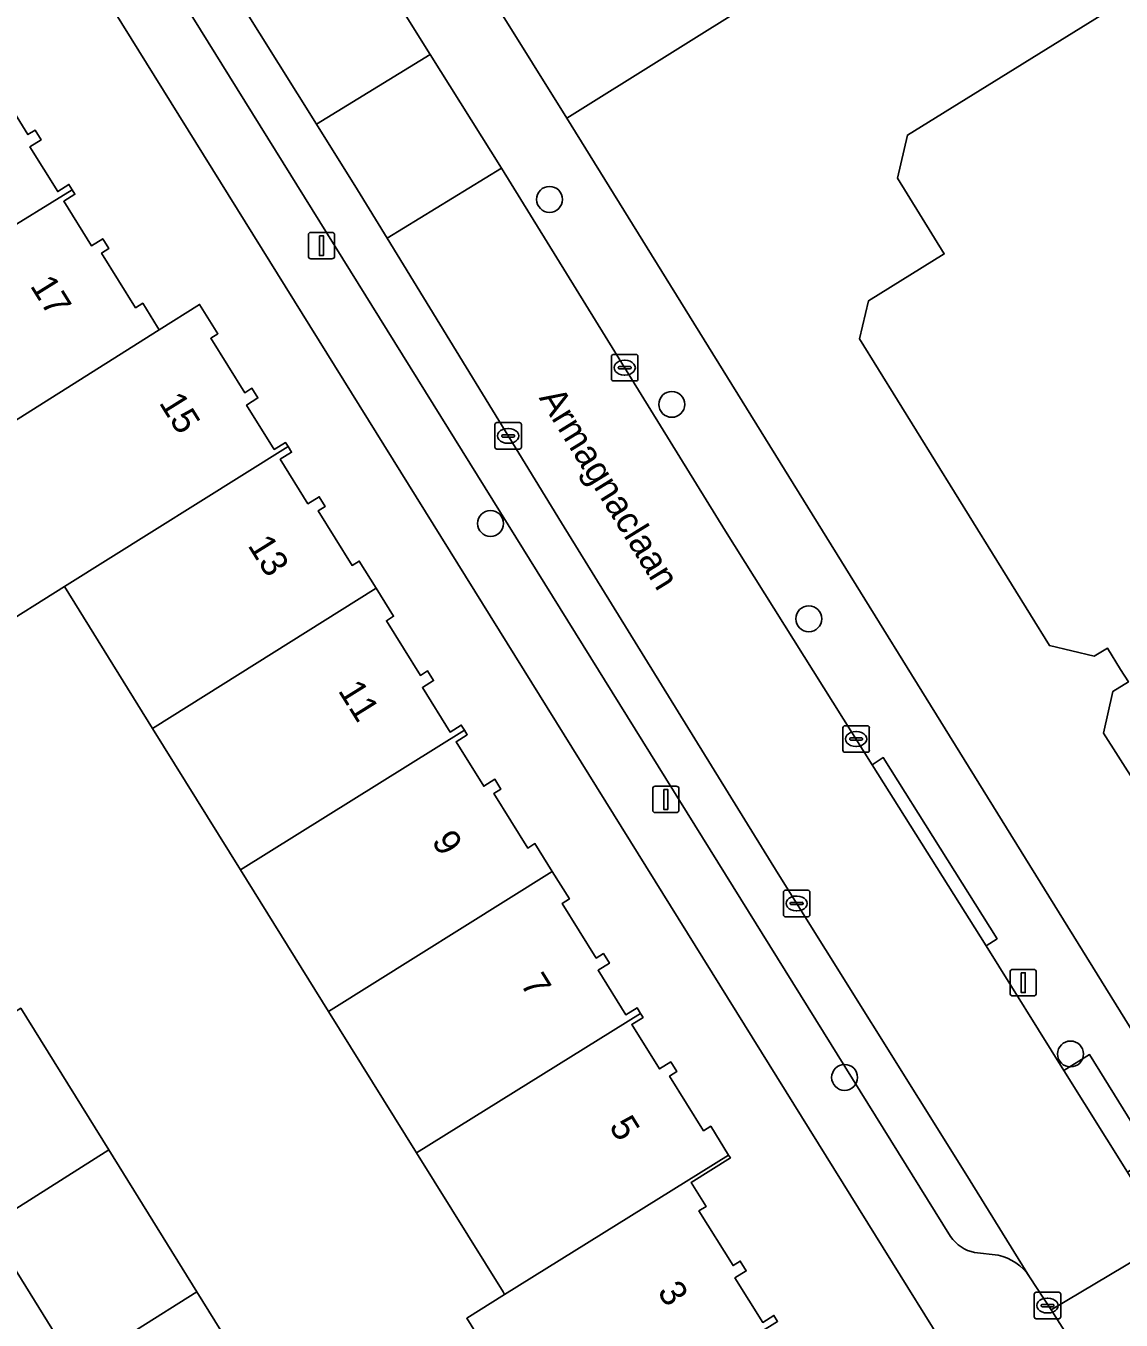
# Model space of a CAD drawing. Extents: x 157767 to 159172, y 387839 to 389425.
# Drawn here: x 158641.28 to 158682.64, y 388021.79 to 388070.65 of the extents above; entities that cross this region are included whole.
import ezdxf

# ---------------------------------------------------------------- set-up
doc = ezdxf.new("R2010")
doc.units = 0
for name, color, linetype in [('IMGEO_Boom', 7, 'Continuous'), ('IMGEO_Erf', 7, 'Continuous'), ('IMGEO_Kolk', 7, 'Continuous'), ('IMGEO_Lichtmast', 7, 'Continuous'), ('IMGEO_Openbare_ruimte_label', 7, 'Continuous'), ('IMGEO_Pand', 7, 'Continuous'), ('IMGEO_Pand_nummerreeks', 7, 'Continuous'), ('IMGEO_Parkeervlak_open', 7, 'Continuous'), ('IMGEO_Rijbaan_lokaal_gesloten', 7, 'Continuous'), ('IMGEO_Rijbaan_lokaal_open', 7, 'Continuous'), ('IMGEO_Voetpad_open', 7, 'Continuous')]:
    doc.layers.add(name, color=color, linetype=linetype)

msp = doc.modelspace()

# ---------------------------------------------------------------- linework, layer by layer
at = {"layer": 'IMGEO_Boom'}
for centre in [(158661.055, 388064.097), (158665.671, 388056.36), (158658.827, 388051.865), (158670.846, 388048.268), (158680.731, 388031.841), (158672.199, 388030.956)]:
    msp.add_circle(centre, 0.489, dxfattribs=at)
at = {"layer": 'IMGEO_Erf'}
for points in [[(158737.779, 388053.263), (158742.17, 388056.603), (158742.727, 388058.158), (158738.82, 388064.497), (158716.081, 388101.143), (158691.111, 388085.534), (158661.715, 388067.158), (158686.368, 388027.385), (158687.799, 388025.086)], [(158683.812, 388041.071), (158681.976, 388043.955), (158682.334, 388045.526), (158682.916, 388045.887), (158682.624, 388046.358), (158682.123, 388047.164), (158681.629, 388046.858), (158679.935, 388047.256), (158672.765, 388058.828), (158673.104, 388060.27), (158675.965, 388062.042), (158674.193, 388064.902), (158674.573, 388066.522), (158688.823, 388075.351)], [(158677.387, 388018.539), (158643.677, 388072.709)], [(158640.071, 388068.608), (158641.358, 388066.541), (158641.63, 388066.711), (158641.857, 388066.345), (158641.432, 388066.079), (158642.481, 388064.395), (158642.906, 388064.66), (158643.027, 388064.464), (158643.133, 388064.294), (158642.707, 388064.027), (158643.757, 388062.345), (158644.182, 388062.609), (158644.409, 388062.243), (158644.137, 388062.072), (158645.424, 388060.006), (158645.695, 388060.175), (158646.256, 388059.274), (158646.318, 388059.175), (158647.842, 388060.135), (158648.531, 388059.028), (158648.259, 388058.858), (158649.543, 388056.797), (158649.814, 388056.967), (158650.041, 388056.601), (158649.616, 388056.336), (158650.662, 388054.657), (158651.086, 388054.921), (158651.182, 388054.766), (158651.313, 388054.555), (158650.888, 388054.29), (158651.934, 388052.611), (158652.358, 388052.874), (158652.585, 388052.51), (158652.313, 388052.339), (158653.597, 388050.279), (158653.868, 388050.447), (158654.506, 388049.424), (158655.168, 388048.361), (158654.897, 388048.191), (158656.181, 388046.13), (158656.45, 388046.299), (158656.678, 388045.934), (158656.254, 388045.668), (158657.3, 388043.989), (158657.723, 388044.253), (158657.844, 388044.058), (158657.95, 388043.888), (158657.526, 388043.623), (158658.572, 388041.943), (158658.995, 388042.207), (158659.222, 388041.841), (158658.95, 388041.672), (158660.234, 388039.61), (158660.505, 388039.78), (158661.159, 388038.73), (158661.805, 388037.694), (158661.533, 388037.524), (158662.817, 388035.463), (158663.088, 388035.632), (158663.316, 388035.266), (158662.891, 388035.001), (158663.937, 388033.322), (158664.36, 388033.585), (158664.496, 388033.368), (158664.588, 388033.221), (158664.163, 388032.955), (158665.209, 388031.275), (158665.632, 388031.54), (158665.86, 388031.174), (158665.588, 388031.004), (158666.872, 388028.943), (158667.143, 388029.112), (158667.82, 388028.023), (158667.887, 388027.916), (158666.405, 388026.994), (158666.971, 388026.085), (158666.699, 388025.914), (158667.985, 388023.851), (158668.256, 388024.02), (158668.483, 388023.654), (158668.059, 388023.389), (158669.105, 388021.707), (158669.529, 388021.972), (158669.67, 388021.746)], [(158641.087, 388033.568), (158644.409, 388028.217), (158647.732, 388022.863), (158651.069, 388017.488), (158646.493, 388014.648), (158645.597, 388010.357), (158647.215, 388007.771), (158649.927, 388009.455), (158652.811, 388011.245), (158658.111, 388002.709), (158666.713, 388008.1), (158664.83, 388011.11), (158664.677, 388011.015), (158662.036, 388015.261), (158661.261, 388016.507), (158657.927, 388021.867), (158659.361, 388022.759), (158659.301, 388022.856), (158656.035, 388028.106), (158652.712, 388033.446), (158649.385, 388038.794), (158646.065, 388044.13), (158642.736, 388049.48), (158640.047, 388047.797)]]:
    msp.add_lwpolyline(points, dxfattribs=at)
at = {"layer": 'IMGEO_Kolk'}
for p, q in [((158663.394, 388057.318), (158663.394, 388058.17)), ((158663.469, 388058.244), (158664.321, 388058.244)), ((158664.395, 388058.17), (158664.395, 388057.318)), ((158663.653, 388057.738), (158663.653, 388057.75)), ((158664.091, 388057.701), (158663.693, 388057.701)), ((158663.696, 388057.787), (158664.094, 388057.787)), ((158663.882, 388058.024), (158663.907, 388058.024)), ((158664.137, 388057.75), (158664.137, 388057.738)), ((158664.321, 388057.244), (158663.469, 388057.244)), ((158663.905, 388057.464), (158663.88, 388057.464)), ((158658.992, 388054.744), (158658.992, 388055.596)), ((158659.067, 388055.67), (158659.919, 388055.67)), ((158659.48, 388055.45), (158659.505, 388055.45)), ((158659.993, 388055.596), (158659.993, 388054.744)), ((158659.251, 388055.164), (158659.251, 388055.176)), ((158659.689, 388055.127), (158659.291, 388055.127)), ((158659.294, 388055.213), (158659.692, 388055.213)), ((158659.503, 388054.89), (158659.478, 388054.89)), ((158659.735, 388055.176), (158659.735, 388055.164)), ((158659.919, 388054.67), (158659.067, 388054.67)), ((158672.132, 388043.303), (158672.132, 388044.155)), ((158672.207, 388044.229), (158673.059, 388044.229)), ((158672.62, 388044.009), (158672.645, 388044.009)), ((158673.133, 388044.155), (158673.133, 388043.303)), ((158672.391, 388043.723), (158672.391, 388043.735)), ((158672.829, 388043.686), (158672.431, 388043.686)), ((158672.434, 388043.772), (158672.832, 388043.772)), ((158672.875, 388043.735), (158672.875, 388043.723)), ((158673.059, 388043.229), (158672.207, 388043.229)), ((158672.643, 388043.449), (158672.618, 388043.449)), ((158669.888, 388037.095), (158669.888, 388037.947)), ((158669.963, 388038.021), (158670.815, 388038.021)), ((158670.376, 388037.801), (158670.401, 388037.801)), ((158670.889, 388037.947), (158670.889, 388037.095)), ((158670.147, 388037.515), (158670.147, 388037.527)), ((158670.585, 388037.478), (158670.187, 388037.478)), ((158670.19, 388037.564), (158670.588, 388037.564)), ((158670.399, 388037.241), (158670.374, 388037.241)), ((158670.631, 388037.527), (158670.631, 388037.515)), ((158670.815, 388037.021), (158669.963, 388037.021)), ((158679.359, 388021.918), (158679.359, 388022.77)), ((158679.434, 388022.844), (158680.286, 388022.844)), ((158679.847, 388022.624), (158679.872, 388022.624)), ((158680.36, 388022.77), (158680.36, 388021.918)), ((158679.618, 388022.338), (158679.618, 388022.35)), ((158680.056, 388022.301), (158679.658, 388022.301)), ((158679.661, 388022.387), (158680.059, 388022.387)), ((158679.87, 388022.064), (158679.845, 388022.064)), ((158680.102, 388022.35), (158680.102, 388022.338)), ((158680.286, 388021.844), (158679.434, 388021.844))]:
    msp.add_line(p, q, dxfattribs=at)
for points in [[(158663.394, 388057.318), (158663.394, 388058.17)], [(158663.469, 388058.244), (158664.321, 388058.244)], [(158664.395, 388058.17), (158664.395, 388057.318)], [(158664.321, 388057.244), (158663.469, 388057.244)], [(158658.992, 388054.744), (158658.992, 388055.596)], [(158659.067, 388055.67), (158659.919, 388055.67)], [(158659.993, 388055.596), (158659.993, 388054.744)], [(158659.919, 388054.67), (158659.067, 388054.67)], [(158672.132, 388043.303), (158672.132, 388044.155)], [(158672.207, 388044.229), (158673.059, 388044.229)], [(158673.133, 388044.155), (158673.133, 388043.303)], [(158673.059, 388043.229), (158672.207, 388043.229)], [(158669.888, 388037.095), (158669.888, 388037.947)], [(158669.963, 388038.021), (158670.815, 388038.021)], [(158670.889, 388037.947), (158670.889, 388037.095)], [(158670.815, 388037.021), (158669.963, 388037.021)], [(158679.359, 388021.918), (158679.359, 388022.77)], [(158679.434, 388022.844), (158680.286, 388022.844)], [(158680.36, 388022.77), (158680.36, 388021.918)], [(158680.286, 388021.844), (158679.434, 388021.844)]]:
    msp.add_lwpolyline(points, dxfattribs=at)
for centre, radius, start, end in [((158663.471, 388058.168), 0.0765, 91.552, 178.448), ((158663.471, 388058.168), 0.0765, 91.552, 178.448), ((158664.319, 388058.168), 0.0765, 1.552, 88.448), ((158664.319, 388058.168), 0.0765, 1.552, 88.448), ((158663.693, 388057.747), 0.0403, 85.8775, 175.7526), ((158663.69, 388057.737), 0.0366, 178.938, 274.7102), ((158664.094, 388057.744), 0.043, 264.8664, 352.4533), ((158664.098, 388057.749), 0.0386, 1.7309, 96.639), ((158663.471, 388057.32), 0.0765, 181.552, 268.448), ((158663.471, 388057.32), 0.0765, 181.552, 268.448), ((158664.319, 388057.32), 0.0765, 271.552, 358.448), ((158664.319, 388057.32), 0.0765, 271.552, 358.448), ((158659.069, 388055.594), 0.0765, 91.552, 178.448), ((158659.069, 388055.594), 0.0765, 91.552, 178.448), ((158659.917, 388055.594), 0.0765, 1.552, 88.448), ((158659.917, 388055.594), 0.0765, 1.552, 88.448), ((158659.069, 388054.746), 0.0765, 181.552, 268.448), ((158659.069, 388054.746), 0.0765, 181.552, 268.448), ((158659.291, 388055.173), 0.0403, 85.8775, 175.7526), ((158659.288, 388055.163), 0.0366, 178.938, 274.7102), ((158659.692, 388055.17), 0.043, 264.8664, 352.4533), ((158659.696, 388055.175), 0.0386, 1.7309, 96.639), ((158659.917, 388054.746), 0.0765, 271.552, 358.448), ((158659.917, 388054.746), 0.0765, 271.552, 358.448), ((158672.209, 388044.153), 0.0765, 91.552, 178.448), ((158672.209, 388044.153), 0.0765, 91.552, 178.448), ((158673.057, 388044.153), 0.0765, 1.552, 88.448), ((158673.057, 388044.153), 0.0765, 1.552, 88.448), ((158672.431, 388043.732), 0.0403, 85.8775, 175.7526), ((158672.428, 388043.722), 0.0366, 178.938, 274.7102), ((158672.832, 388043.729), 0.043, 264.8664, 352.4533), ((158672.836, 388043.734), 0.0386, 1.7309, 96.639), ((158672.209, 388043.305), 0.0765, 181.552, 268.448), ((158672.209, 388043.305), 0.0765, 181.552, 268.448), ((158673.057, 388043.305), 0.0765, 271.552, 358.448), ((158673.057, 388043.305), 0.0765, 271.552, 358.448), ((158669.965, 388037.945), 0.0765, 91.552, 178.448), ((158669.965, 388037.945), 0.0765, 91.552, 178.448), ((158670.813, 388037.945), 0.0765, 1.552, 88.448), ((158670.813, 388037.945), 0.0765, 1.552, 88.448), ((158670.187, 388037.524), 0.0403, 85.8775, 175.7526), ((158670.184, 388037.514), 0.0366, 178.938, 274.7102), ((158670.588, 388037.521), 0.043, 264.8664, 352.4533), ((158670.592, 388037.526), 0.0386, 1.7309, 96.639), ((158669.965, 388037.097), 0.0765, 181.552, 268.448), ((158669.965, 388037.097), 0.0765, 181.552, 268.448), ((158670.813, 388037.097), 0.0765, 271.552, 358.448), ((158670.813, 388037.097), 0.0765, 271.552, 358.448), ((158679.436, 388022.768), 0.0765, 91.552, 178.448), ((158679.436, 388022.768), 0.0765, 91.552, 178.448), ((158680.284, 388022.768), 0.0765, 1.552, 88.448), ((158680.284, 388022.768), 0.0765, 1.552, 88.448), ((158679.658, 388022.347), 0.0403, 85.8775, 175.7526), ((158679.655, 388022.337), 0.0366, 178.938, 274.7102), ((158680.059, 388022.344), 0.043, 264.8664, 352.4533), ((158680.063, 388022.349), 0.0386, 1.7309, 96.639), ((158679.436, 388021.92), 0.0765, 181.552, 268.448), ((158679.436, 388021.92), 0.0765, 181.552, 268.448), ((158680.284, 388021.92), 0.0765, 271.552, 358.448), ((158680.284, 388021.92), 0.0765, 271.552, 358.448)]:
    msp.add_arc(centre, radius, start, end, dxfattribs=at)
for centre, major_axis, ratio, start_param, end_param in [((158663.881, 388057.744), (-0.387, 0.002), 0.722429, 4.712389, 7.853982), ((158663.906, 388057.744), (-0.39, 0.002), 0.717154, 1.570796, 4.712389), ((158659.479, 388055.17), (-0.387, 0.002), 0.722429, 4.712389, 7.853982), ((158659.504, 388055.17), (-0.39, 0.002), 0.717154, 1.570796, 4.712389), ((158672.619, 388043.729), (-0.387, 0.002), 0.722429, 4.712389, 7.853982), ((158672.644, 388043.729), (-0.39, 0.002), 0.717154, 1.570796, 4.712389), ((158670.375, 388037.521), (-0.387, 0.002), 0.722429, 4.712389, 7.853982), ((158670.4, 388037.521), (-0.39, 0.002), 0.717154, 1.570796, 4.712389), ((158679.846, 388022.344), (-0.387, 0.002), 0.722429, 4.712389, 7.853982), ((158679.871, 388022.344), (-0.39, 0.002), 0.717154, 1.570796, 4.712389)]:
    msp.add_ellipse(centre, major_axis=major_axis, ratio=ratio, start_param=start_param, end_param=end_param, dxfattribs=at)
at = {"layer": 'IMGEO_Lichtmast'}
for p, q in [((158651.947, 388061.953), (158651.947, 388062.753)), ((158651.947, 388062.753), (158651.947, 388061.953)), ((158652.047, 388062.853), (158652.837, 388062.853)), ((158652.837, 388062.853), (158652.047, 388062.853)), ((158652.937, 388062.753), (158652.937, 388061.953)), ((158652.937, 388061.953), (158652.937, 388062.753)), ((158652.837, 388061.853), (158652.047, 388061.853)), ((158652.047, 388061.853), (158652.837, 388061.853)), ((158664.951, 388041.049), (158664.951, 388041.849)), ((158664.951, 388041.849), (158664.951, 388041.049)), ((158665.051, 388041.949), (158665.841, 388041.949)), ((158665.841, 388041.949), (158665.051, 388041.949)), ((158665.941, 388041.849), (158665.941, 388041.049)), ((158665.941, 388041.049), (158665.941, 388041.849)), ((158665.841, 388040.949), (158665.051, 388040.949)), ((158665.051, 388040.949), (158665.841, 388040.949)), ((158678.449, 388034.132), (158678.449, 388034.932)), ((158678.449, 388034.932), (158678.449, 388034.132)), ((158678.549, 388035.032), (158679.339, 388035.032)), ((158679.339, 388035.032), (158678.549, 388035.032)), ((158679.439, 388034.932), (158679.439, 388034.132)), ((158679.439, 388034.132), (158679.439, 388034.932)), ((158679.339, 388034.032), (158678.549, 388034.032)), ((158678.549, 388034.032), (158679.339, 388034.032))]:
    msp.add_line(p, q, dxfattribs=at)
for points in [[(158652.367, 388062.728), (158652.517, 388062.728), (158652.517, 388061.978), (158652.367, 388061.978), (158652.367, 388062.728)], [(158665.371, 388041.824), (158665.521, 388041.824), (158665.521, 388041.074), (158665.371, 388041.074), (158665.371, 388041.824)], [(158678.869, 388034.907), (158679.019, 388034.907), (158679.019, 388034.157), (158678.869, 388034.157), (158678.869, 388034.907)]]:
    msp.add_lwpolyline(points, dxfattribs=at)
for centre, start, end in [((158652.047, 388062.753), 90, 180), ((158652.047, 388062.753), 90, 180), ((158652.837, 388062.753), 0, 90), ((158652.837, 388062.753), 360, 90), ((158652.047, 388061.953), 180, 270), ((158652.047, 388061.953), 180, 270), ((158652.837, 388061.953), 270, 0), ((158652.837, 388061.953), 270, 0), ((158665.051, 388041.849), 90, 180), ((158665.051, 388041.849), 90, 180), ((158665.841, 388041.849), 0, 90), ((158665.841, 388041.849), 360, 90), ((158665.051, 388041.049), 180, 270), ((158665.051, 388041.049), 180, 270), ((158665.841, 388041.049), 270, 0), ((158665.841, 388041.049), 270, 0), ((158678.549, 388034.932), 90, 180), ((158678.549, 388034.932), 90, 180), ((158679.339, 388034.932), 0, 90), ((158679.339, 388034.932), 360, 90), ((158678.549, 388034.132), 180, 270), ((158678.549, 388034.132), 180, 270), ((158679.339, 388034.132), 270, 0), ((158679.339, 388034.132), 270, 0)]:
    msp.add_arc(centre, 0.1, start, end, dxfattribs=at)
at = {"layer": 'IMGEO_Pand'}
msp.add_lwpolyline([(158688.823, 388075.351), (158674.573, 388066.522), (158674.193, 388064.902), (158675.965, 388062.042), (158673.104, 388060.27), (158672.765, 388058.828), (158679.935, 388047.256), (158681.629, 388046.858), (158682.123, 388047.164), (158682.624, 388046.358), (158682.916, 388045.887), (158682.334, 388045.526), (158681.976, 388043.955), (158683.812, 388041.071)], dxfattribs=at)
for points in [[(158634.439, 388059.172), (158643.027, 388064.464), (158642.906, 388064.66), (158642.481, 388064.395), (158641.432, 388066.079), (158641.857, 388066.345), (158641.63, 388066.711), (158641.358, 388066.541), (158640.071, 388068.608), (158640.344, 388068.778), (158639.602, 388069.968), (158631.037, 388064.64), (158631.195, 388064.385)], [(158646.318, 388059.175), (158646.256, 388059.274), (158645.695, 388060.175), (158645.424, 388060.006), (158644.137, 388062.072), (158644.409, 388062.243), (158644.182, 388062.609), (158643.757, 388062.345), (158642.707, 388064.027), (158643.133, 388064.294), (158643.027, 388064.464), (158634.439, 388059.172), (158631.977, 388057.64), (158631.722, 388057.482), (158634.364, 388053.237), (158635.075, 388052.093), (158636.713, 388053.125)], [(158651.182, 388054.766), (158651.086, 388054.921), (158650.662, 388054.657), (158649.616, 388056.336), (158650.041, 388056.601), (158649.814, 388056.967), (158649.543, 388056.797), (158648.259, 388058.858), (158648.531, 388059.028), (158647.842, 388060.135), (158646.318, 388059.175), (158636.713, 388053.125), (158640.047, 388047.797), (158642.736, 388049.48)], [(158642.736, 388049.48), (158646.065, 388044.13), (158654.506, 388049.424), (158653.868, 388050.447), (158653.597, 388050.279), (158652.313, 388052.339), (158652.585, 388052.51), (158652.358, 388052.874), (158651.934, 388052.611), (158650.888, 388054.29), (158651.313, 388054.555), (158651.182, 388054.766)], [(158649.385, 388038.794), (158657.844, 388044.058), (158657.723, 388044.253), (158657.3, 388043.989), (158656.254, 388045.668), (158656.678, 388045.934), (158656.45, 388046.299), (158656.181, 388046.13), (158654.897, 388048.191), (158655.168, 388048.361), (158654.506, 388049.424), (158646.065, 388044.13)], [(158649.385, 388038.794), (158652.712, 388033.446), (158661.159, 388038.73), (158660.505, 388039.78), (158660.234, 388039.61), (158658.95, 388041.672), (158659.222, 388041.841), (158658.995, 388042.207), (158658.572, 388041.943), (158657.526, 388043.623), (158657.95, 388043.888), (158657.844, 388044.058)], [(158664.496, 388033.368), (158664.36, 388033.585), (158663.937, 388033.322), (158662.891, 388035.001), (158663.316, 388035.266), (158663.088, 388035.632), (158662.817, 388035.463), (158661.533, 388037.524), (158661.805, 388037.694), (158661.159, 388038.73), (158652.712, 388033.446), (158656.035, 388028.106)], [(158639.851, 388025.347), (158644.409, 388028.217), (158641.087, 388033.568), (158636.529, 388030.698)], [(158667.82, 388028.023), (158667.143, 388029.112), (158666.872, 388028.943), (158665.588, 388031.004), (158665.86, 388031.174), (158665.632, 388031.54), (158665.209, 388031.275), (158664.163, 388032.955), (158664.588, 388033.221), (158664.496, 388033.368), (158656.035, 388028.106), (158659.301, 388022.856), (158659.361, 388022.759)], [(158647.732, 388022.863), (158644.409, 388028.217), (158639.851, 388025.347), (158643.178, 388019.988)], [(158668.059, 388023.389), (158668.483, 388023.654), (158668.256, 388024.02), (158667.985, 388023.851), (158666.699, 388025.914), (158666.971, 388026.085), (158666.405, 388026.994), (158667.887, 388027.916), (158667.82, 388028.023), (158659.361, 388022.759), (158657.927, 388021.867), (158661.261, 388016.507), (158669.67, 388021.746), (158669.529, 388021.972), (158669.105, 388021.707)], [(158647.732, 388022.863), (158643.178, 388019.988), (158646.493, 388014.648), (158651.069, 388017.488)]]:
    msp.add_lwpolyline(points, close=True, dxfattribs=at)
at = {"layer": 'IMGEO_Parkeervlak_open'}
for points in [[(158654.918, 388062.634), (158653.8, 388064.458), (158652.251, 388066.934), (158647.23, 388074.96), (158647.017, 388075.274)], [(158647.011, 388071.904), (158676.204, 388024.951)], [(158679.187, 388023.431), (158676.773, 388027.319), (158669.687, 388038.645), (158661.503, 388051.892), (158654.918, 388062.634)], [(158677.11, 388024.344), (158677.997, 388024.244)]]:
    msp.add_lwpolyline(points, dxfattribs=at)
for centre, radius, start, end in [((158677.416, 388025.78), 1.469, 214.3842, 257.9734), ((158677.595, 388022.379), 1.908, 33.4676, 77.8512)]:
    msp.add_arc(centre, radius, start, end, dxfattribs=at)
at = {"layer": 'IMGEO_Rijbaan_lokaal_gesloten'}
msp.add_lwpolyline([(158685.23, 388023.562), (158684.417, 388024.818), (158680.002, 388022.18), (158682.643, 388018.022), (158684.22, 388015.539), (158684.312, 388015.394), (158685.259, 388013.888), (158685.259, 388013.888)], dxfattribs=at)
at = {"layer": 'IMGEO_Rijbaan_lokaal_open'}
for points in [[(158691.111, 388085.534), (158690.32, 388086.769), (158690.206, 388086.917), (158688.634, 388089.454), (158683.429, 388086.43), (158677.93, 388083.013), (158673.608, 388080.326), (158659.117, 388071.321), (158661.715, 388067.158)], [(158652.251, 388066.934), (158653.8, 388064.458), (158654.918, 388062.634), (158659.242, 388065.28), (158656.553, 388069.567)], [(158684.155, 388025.223), (158683.4, 388026.547), (158682.878, 388027.382), (158680.483, 388031.211), (158677.539, 388035.917), (158673.241, 388042.758), (158667.7, 388051.578), (158659.242, 388065.28), (158654.918, 388062.634), (158661.503, 388051.892), (158669.687, 388038.645), (158676.773, 388027.319), (158679.187, 388023.431), (158680.002, 388022.18), (158684.417, 388024.818)]]:
    msp.add_lwpolyline(points, close=True, dxfattribs=at)
for points in [[(158647.017, 388075.274), (158647.23, 388074.96), (158652.251, 388066.934), (158656.553, 388069.567), (158650.265, 388079.623)], [(158634.286, 388021.267), (158641.958, 388009.019), (158642.158, 388009.189), (158647.915, 388000), (158649.662, 387997.212), (158652.572, 387999.219), (158652.076, 388000), (158651.768, 388000.44), (158647.215, 388007.771), (158645.597, 388010.357), (158646.493, 388014.648), (158643.178, 388019.988), (158639.851, 388025.347)]]:
    msp.add_lwpolyline(points, dxfattribs=at)
at = {"layer": 'IMGEO_Voetpad_open'}
for points in [[(158686.368, 388027.385), (158661.715, 388067.158), (158659.117, 388071.321), (158646.863, 388091.033), (158646.674, 388090.915), (158645.347, 388090.085), (158594.021, 388057.981)], [(158650.265, 388079.623), (158656.553, 388069.567), (158659.242, 388065.28), (158667.7, 388051.578), (158673.241, 388042.758), (158673.661, 388043.028), (158677.959, 388036.187), (158677.539, 388035.917), (158680.483, 388031.211), (158681.448, 388031.815), (158683.827, 388027.985), (158682.878, 388027.382), (158683.4, 388026.547), (158684.155, 388025.223), (158684.545, 388025.492), (158685.577, 388023.981)], [(158643.677, 388072.709), (158677.387, 388018.539)], [(158676.204, 388024.951), (158647.011, 388071.904)], [(158677.997, 388024.244), (158677.11, 388024.344)], [(158677.812, 388017.498), (158680.693, 388013.033), (158683.235, 388014.918), (158684.22, 388015.539), (158682.643, 388018.022), (158680.002, 388022.18), (158679.187, 388023.431)]]:
    msp.add_lwpolyline(points, dxfattribs=at)
for points in [[(158677.539, 388035.917), (158677.959, 388036.187), (158673.661, 388043.028), (158673.241, 388042.758)], [(158682.878, 388027.382), (158683.827, 388027.985), (158681.448, 388031.815), (158680.483, 388031.211)]]:
    msp.add_lwpolyline(points, close=True, dxfattribs=at)
for centre, radius, start, end in [((158677.416, 388025.78), 1.469, 214.3842, 257.9734), ((158677.595, 388022.379), 1.908, 33.4676, 77.8512)]:
    msp.add_arc(centre, radius, start, end, dxfattribs=at)

# ---------------------------------------------------------------- texts
at = {"layer": 'IMGEO_Openbare_ruimte_label'}
msp.add_text('Armagnaclaan', height=1, rotation=301.6225, dxfattribs=at).set_placement((158660.639, 388056.604))
at = {"layer": 'IMGEO_Pand_nummerreeks'}
for s, rotation, p in [('17', 301.8906, (158641.418, 388060.838)), ('15', 301.8849, (158646.287, 388056.424)), ('13', 301.8878, (158649.637, 388051.04)), ('11', 301.8878, (158653.048, 388045.558)), ('9', 301.8878, (158656.581, 388039.879)), ('7', 301.8878, (158659.931, 388034.494)), ('5', 301.8849, (158663.282, 388029.109)), ('3', 301.8849, (158665.107, 388022.871))]:
    msp.add_text(s, height=1, rotation=rotation, dxfattribs=at).set_placement(p)

doc.saveas('drawing.dxf')
